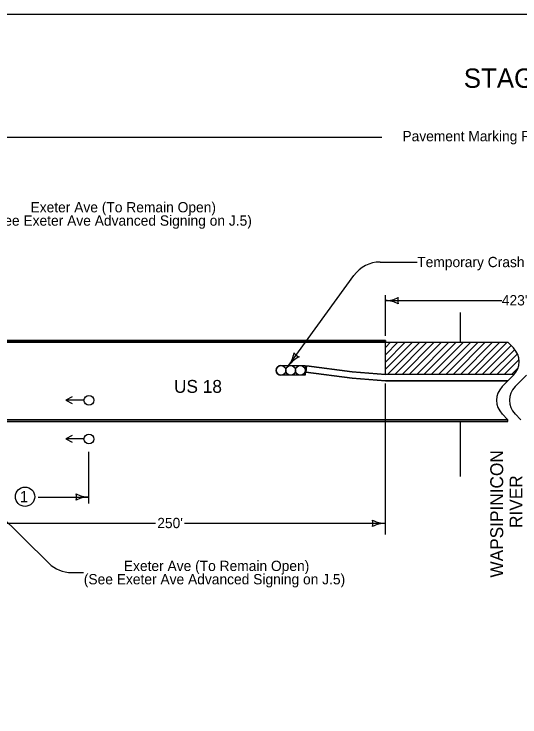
# Model space of a CAD drawing. Extents: x -2134934 to -2122394, y -2140205 to -2137036.
# Drawn here: x -2134151 to -2133366, y -2138126 to -2137036 of the extents above; entities that cross this region are included whole.
import ezdxf

# ---------------------------------------------------------------- set-up
doc = ezdxf.new("R2010")
doc.units = 0
for name, color, linetype in [('Barrier', 7, 'Continuous'), ('BridgeSuperStructureExisting', 7, 'Continuous'), ('Default', 7, 'Continuous'), ('dsnCellsNorthArrow', 7, 'Continuous'), ('DsnShtPlotIdentification', 7, 'Continuous'), ('DsnShtPlotShape', 7, 'Continuous')]:
    doc.layers.add(name, color=color, linetype=linetype)

msp = doc.modelspace()

# ---------------------------------------------------------------- linework, layer by layer
at = {"layer": 'BridgeSuperStructureExisting'}
for p, q in [((-2134239.4, -2137227), (-2133580, -2137227)), ((-2133582.7, -2137420.6), (-2133525, -2137420.6)), ((-2133724.1, -2137580.8), (-2133623.3, -2137441.3)), ((-2133574.4, -2137535.2), (-2133574.4, -2137471.9)), ((-2133574.4, -2137480.5), (-2133393.8, -2137480.5)), ((-2133458.6, -2137498.8), (-2133458.6, -2137545.2)), ((-2133574.4, -2137545.2), (-2134884.4, -2137545.2)), ((-2133574.4, -2137553.2), (-2133566.4, -2137545.2)), ((-2133574.4, -2137564.5), (-2133555.1, -2137545.2)), ((-2133574.4, -2137575.8), (-2133543.8, -2137545.2)), ((-2133574.4, -2137595.2), (-2133574.4, -2137545.2)), ((-2133574.4, -2137587.1), (-2133532.5, -2137545.2)), ((-2133574.4, -2137595.2), (-2133574.4, -2137545.2)), ((-2133571.2, -2137595.2), (-2133521.2, -2137545.2)), ((-2133559.9, -2137595.2), (-2133509.9, -2137545.2)), ((-2133548.6, -2137595.2), (-2133498.6, -2137545.2)), ((-2133537.3, -2137595.2), (-2133487.3, -2137545.2)), ((-2133525.9, -2137595.2), (-2133475.9, -2137545.2)), ((-2133514.6, -2137595.2), (-2133464.6, -2137545.2)), ((-2133453.3, -2137545.2), (-2133503.3, -2137595.2)), ((-2133492, -2137595.2), (-2133442, -2137545.2)), ((-2133480.7, -2137595.2), (-2133430.7, -2137545.2)), ((-2133469.4, -2137595.2), (-2133419.4, -2137545.2)), ((-2133458.1, -2137595.2), (-2133408.1, -2137545.2)), ((-2133446.7, -2137595.2), (-2133396.7, -2137545.2)), ((-2133435.4, -2137595.2), (-2133385.4, -2137545.2)), ((-2133424.1, -2137595.2), (-2133379.3, -2137550.3)), ((-2133375.7, -2137553.9), (-2133384.4, -2137545.2)), ((-2133412.8, -2137595.2), (-2133373.7, -2137556.1)), ((-2133401.5, -2137595.2), (-2133369.4, -2137563.1)), ((-2133390.2, -2137595.2), (-2133367, -2137572)), ((-2133736.5, -2137581.3), (-2133699, -2137581.3)), ((-2133736.5, -2137581.3), (-2133699, -2137581.3)), ((-2133699, -2137581.3), (-2133699, -2137596.3)), ((-2133699, -2137581.3), (-2133699, -2137596.3)), ((-2133696.7, -2137581.7), (-2133698, -2137591.5)), ((-2133696.7, -2137581.7), (-2133698, -2137591.5)), ((-2133698, -2137591.5), (-2133696.7, -2137581.7)), ((-2133698, -2137591.5), (-2133696.7, -2137581.7)), ((-2133626.2, -2137590.8), (-2133696.7, -2137581.7)), ((-2133626.2, -2137590.8), (-2133696.7, -2137581.7)), ((-2133626.2, -2137590.8), (-2133696.7, -2137581.7)), ((-2133696.7, -2137581.7), (-2133626.2, -2137590.8)), ((-2133378.9, -2137595.2), (-2133368.4, -2137584.7)), ((-2133699, -2137596.3), (-2133736.5, -2137596.3)), ((-2133699, -2137596.3), (-2133736.5, -2137596.3)), ((-2133698, -2137591.5), (-2133626, -2137600.8)), ((-2133626, -2137600.8), (-2133698, -2137591.5)), ((-2133626, -2137600.8), (-2133698, -2137591.5)), ((-2133697.9, -2137591.5), (-2133626, -2137600.8)), ((-2133574.1, -2137595.2), (-2133626.2, -2137590.8)), ((-2133574.4, -2137595.1), (-2133626.2, -2137590.8)), ((-2133574.4, -2137595.2), (-2133626.2, -2137590.8)), ((-2133626.2, -2137590.8), (-2133574.4, -2137595.2)), ((-2133574.4, -2137595.2), (-2133574.4, -2137595.1)), ((-2133574.2, -2137595.2), (-2133574.4, -2137595.2)), ((-2133374.5, -2137595.2), (-2133574.4, -2137595.2)), ((-2133574.1, -2137595.2), (-2133574.2, -2137595.2)), ((-2133374.5, -2137595.2), (-2133574.1, -2137595.2)), ((-2133393.2, -2137613.9), (-2133375.7, -2137596.4)), ((-2133384.4, -2137605.2), (-2133375.7, -2137596.4)), ((-2133373.2, -2137613.9), (-2133355.7, -2137596.4)), ((-2133626, -2137600.8), (-2133574.4, -2137605.2)), ((-2133626, -2137600.8), (-2133574.4, -2137605.2)), ((-2133574.4, -2137605.2), (-2133626, -2137600.8)), ((-2133574.4, -2137605.2), (-2133626, -2137600.8)), ((-2133574.4, -2137605.2), (-2133384.4, -2137605.2)), ((-2133574.4, -2137605.2), (-2133384.4, -2137605.2)), ((-2133384.4, -2137605.2), (-2133574.4, -2137605.2)), ((-2133384.4, -2137605.2), (-2133574.4, -2137605.2)), ((-2133393.2, -2137613.9), (-2133384.4, -2137605.2)), ((-2133574.4, -2137843.1), (-2133574.4, -2137609.3)), ((-2134042.2, -2137634.8), (-2134070.1, -2137634.8)), ((-2133384.4, -2137665.2), (-2133393.2, -2137656.4)), ((-2133384.4, -2137665.2), (-2133393.2, -2137656.4)), ((-2133364.4, -2137665.2), (-2133373.2, -2137656.4)), ((-2133373.2, -2137656.4), (-2133364.4, -2137665.2)), ((-2134884.4, -2137665.2), (-2133384.4, -2137665.2)), ((-2133458.6, -2137668.2), (-2133458.6, -2137753.6)), ((-2134042.2, -2137694.8), (-2134070.1, -2137694.8)), ((-2134096.5, -2137887.9), (-2134284.7, -2137702.6)), ((-2134034.4, -2137795.2), (-2134034.4, -2137715.2)), ((-2134113.2, -2137785.2), (-2134034.4, -2137785.2)), ((-2134234.4, -2137826), (-2133930.9, -2137826)), ((-2133886, -2137826), (-2133574.4, -2137826)), ((-2133851.4, -2137826), (-2133801.8, -2137826)), ((-2134061.4, -2137902.3), (-2134043, -2137902.3))]:
    msp.add_line(p, q, dxfattribs=at)
for points in [[(-2133574.4, -2137545.2), (-2133384.4, -2137545.2)], [(-2133736.5, -2137581.3), (-2133736.5, -2137581.3)], [(-2133736.5, -2137596.3), (-2133736.5, -2137596.3)], [(-2133574.1, -2137595.2), (-2133574.1, -2137595.2)], [(-2133384.4, -2137605.2), (-2133384.4, -2137605.2)], [(-2133384.4, -2137605.2), (-2133384.4, -2137605.2)], [(-2133364.4, -2137605.2), (-2133364.4, -2137605.2), (-2133373.2, -2137613.9)], [(-2134060.5, -2137630), (-2134070.5, -2137635), (-2134060.5, -2137640)], [(-2134060.5, -2137690), (-2134070.5, -2137695), (-2134060.5, -2137700)]]:
    msp.add_lwpolyline(points, dxfattribs=at)
for centre, radius in [((-2133736.5, -2137588.8), 7.5), ((-2133736.5, -2137588.8), 7.5), ((-2133721.5, -2137588.8), 7.5), ((-2133721.5, -2137588.8), 7.5), ((-2133706.5, -2137588.8), 7.5), ((-2133706.5, -2137588.8), 7.5), ((-2134034.4, -2137635.2), 7.74), ((-2134034.4, -2137695.2), 7.74), ((-2134133.6, -2137784.7), 15)]:
    msp.add_circle(centre, radius, dxfattribs=at)
for centre, radius, start, end in [((-2133582.7, -2137470.6), 50, 90, 144.138), ((-2133574.4, -2137438), 42.5, 270, 298.0725), ((-2133538.8, -2137480.5), 16.4, 162.2666, 197.7334), ((-2133574.4, -2137523), 42.5, 61.9275, 90), ((-2133396.9, -2137575.2), 30, 315, 45), ((-2133736.5, -2137588.8), 7.5, 90.0028, 269.9972), ((-2133396.9, -2137575.2), 30, 315, 318.1884), ((-2133372, -2137635.2), 30, 135, 225), ((-2133372, -2137635.2), 30, 135, 225), ((-2133352, -2137635.2), 30, 135, 225), ((-2133352, -2137635.2), 30, 135, 225), ((-2134070.1, -2137785.2), 16.4, 342.2666, 17.7333), ((-2134034.4, -2137742.7), 42.5, 241.9275, 270), ((-2134034.4, -2137827.7), 42.5, 90, 118.0725), ((-2134061.4, -2137852.3), 50, 225.4365, 270)]:
    msp.add_arc(centre, radius, start, end, dxfattribs=at)
at = {"layer": 'Default'}
msp.add_lwpolyline([(-2134934.4, -2137035.9), (-2131799.4, -2137035.9), (-2131799.4, -2139045.9), (-2134934.4, -2139045.9)], close=True, dxfattribs=at)
at = {"layer": 'DsnShtPlotIdentification'}
for p, q in [((-2133766.5, -2137542.2), (-2134239.4, -2137542.2)), ((-2133574.4, -2137542.2), (-2133766.5, -2137542.2)), ((-2133766.5, -2137542.2), (-2133764.3, -2137545.2)), ((-2133764.3, -2137545.2), (-2133766.5, -2137542.2)), ((-2133574.4, -2137545.2), (-2133574.4, -2137542.2)), ((-2133574.4, -2137542.2), (-2133574.4, -2137545.2)), ((-2134239.4, -2137545.2), (-2133764.3, -2137545.2)), ((-2134884.4, -2137665.2), (-2133384.4, -2137665.2)), ((-2134884.4, -2137665.2), (-2133384.4, -2137665.2)), ((-2134884.4, -2137668.2), (-2133384.4, -2137668.2)), ((-2134884.4, -2137668.2), (-2133384.4, -2137668.2)), ((-2133384.4, -2137665.2), (-2134234.4, -2137665.2)), ((-2133384.4, -2137668.2), (-2133384.4, -2137665.2)), ((-2133384.4, -2137668.2), (-2133384.4, -2137665.2))]:
    msp.add_line(p, q, dxfattribs=at)
for points in [[(-2134884.4, -2137542.2), (-2133574.4, -2137542.2)], [(-2134884.9, -2137545.2), (-2133574.9, -2137545.2)], [(-2134884.4, -2137545.2), (-2133574.4, -2137545.2)], [(-2133764.3, -2137545.2), (-2133574.9, -2137545.2), (-2133574.4, -2137545.2)]]:
    msp.add_lwpolyline(points, dxfattribs=at)
at = {"layer": 'DsnShtPlotShape'}
for centre, radius, start, end in [((-2133758.3, -2137555.6), 42.5, 323.701, 351.7735), ((-2133703, -2137552.1), 16.4, 215.9676, 251.4343), ((-2133689.8, -2137606), 42.5, 115.6285, 143.701), ((-2133610.1, -2137826), 16.4, 342.2666, 17.7333), ((-2133574.4, -2137783.5), 42.5, 241.9275, 270), ((-2133574.4, -2137868.5), 42.5, 90, 118.0725)]:
    msp.add_arc(centre, radius, start, end, dxfattribs=at)

# ---------------------------------------------------------------- texts
at = {"layer": 'Barrier'}
msp.add_text('STAGE 2', height=30, dxfattribs=at).set_placement((-2133452.8, -2137150.4))
at = {"layer": 'BridgeSuperStructureExisting'}
for s, height, p in [('Pavement Marking Removal Limits', 16, (-2133548, -2137233.3)), ('Exeter Ave (To Remain Open)', 16, (-2134125.1, -2137343.6)), ('(See Exeter Ave Advanced Signing on J.5)', 16, (-2134187.2, -2137364.3)), ('Temporary Crash Cushion', 16, (-2133525, -2137428.6)), ("423'", 16, (-2133393.8, -2137488)), ('1', 17.5, (-2134141.7, -2137793.4)), ("250'", 16, (-2133928.4, -2137833.5)), ('Exeter Ave (To Remain Open)', 16, (-2133980.3, -2137900)), ('(See Exeter Ave Advanced Signing on J.5)', 16, (-2134042.4, -2137920.7))]:
    msp.add_text(s, height=height, dxfattribs=at).set_placement(p)
at = {"layer": 'dsnCellsNorthArrow'}
msp.add_text('US 18', height=20, dxfattribs=at).set_placement((-2133902.4, -2137623.6))
for s, p in [('WAPSIPINICON ', (-2133391.7, -2137910.2)), ('RIVER', (-2133361.7, -2137833.2))]:
    msp.add_text(s, height=20, rotation=90, dxfattribs=at).set_placement(p)

doc.saveas('drawing.dxf')
